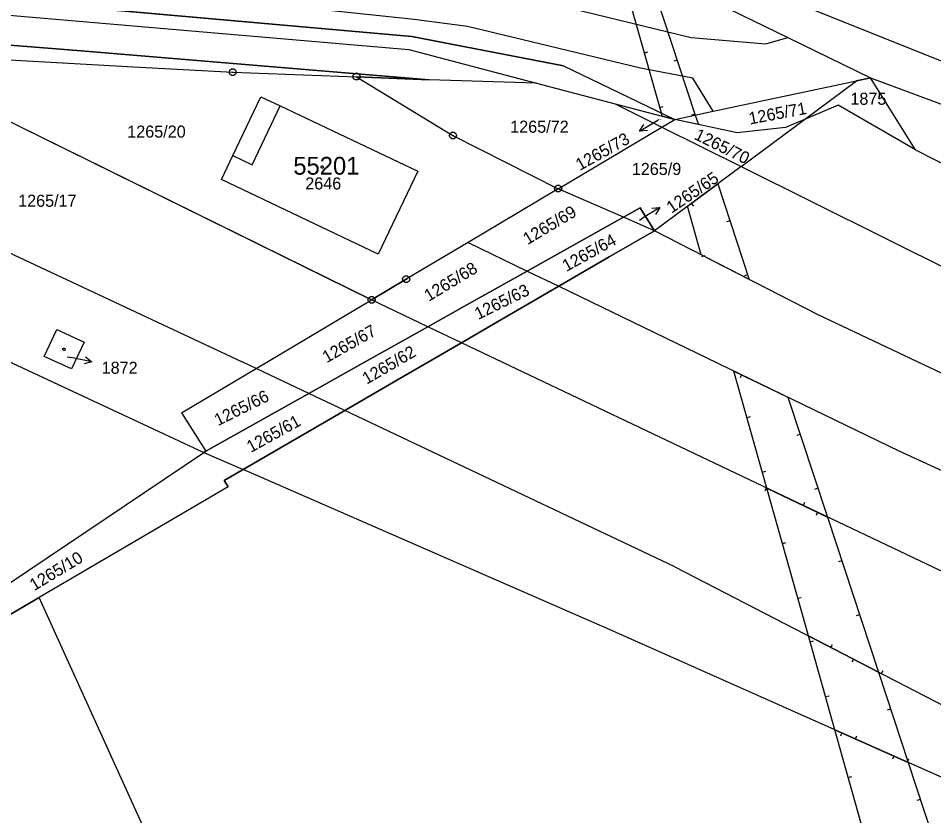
# Model space of a CAD drawing. Extents: x -779618 to -776429, y -1144546 to -1143350.
# Drawn here: x -777090.7 to -776962, y -1143980.2 to -1143868 of the extents above; entities that cross this region are included whole.
import ezdxf

# ---------------------------------------------------------------- set-up
doc = ezdxf.new("R2010")
doc.units = 0
for name, color, linetype in [('1', 7, 'Continuous'), ('11', 7, 'Continuous'), ('12', 7, 'Continuous'), ('13', 7, 'Continuous'), ('2', 7, 'Continuous'), ('4', 7, 'Continuous'), ('5', 7, 'Continuous'), ('6', 7, 'Continuous'), ('7', 7, 'Continuous'), ('8', 7, 'Continuous')]:
    doc.layers.add(name, color=color, linetype=linetype)

msp = doc.modelspace()

# ---------------------------------------------------------------- linework, layer by layer
at = {"layer": '1'}
for p, q in [((-777035.36, -1143870.54), (-777167.58, -1143858.82)), ((-777002.25, -1143861.05), (-776982.48, -1143870.69)), ((-777150.77, -1143862.48), (-777035.76, -1143872.38)), ((-777082.45, -1143872.54), (-777124.98, -1143869.13)), ((-777014.02, -1143874.66), (-777035.36, -1143870.54)), ((-776982.48, -1143870.69), (-776970.83, -1143876.37)), ((-777032.92, -1143876.65), (-777082.45, -1143872.54)), ((-777035.76, -1143872.38), (-777017.82, -1143877.1)), ((-777098.28, -1143873.49), (-777074.51, -1143874.84)), ((-777074.51, -1143874.84), (-777060.56, -1143875.59)), ((-777014.02, -1143874.66), (-776998.39, -1143882.22)), ((-777060.56, -1143875.59), (-777043.14, -1143876.21)), ((-777043.14, -1143876.21), (-777032.92, -1143876.65)), ((-777043.14, -1143876.21), (-777029.58, -1143884.49)), ((-777017.82, -1143877.1), (-777032.92, -1143876.65)), ((-776970.83, -1143876.37), (-776972.79, -1143876.78)), ((-776964.5, -1143886.48), (-776970.83, -1143876.37)), ((-776970.83, -1143876.37), (-776959.34, -1143880.62)), ((-777017.82, -1143877.1), (-777006.74, -1143880.02)), ((-776992.99, -1143881.07), (-776972.79, -1143876.78)), ((-776980.14, -1143882.23), (-776972.79, -1143876.78)), ((-777100.29, -1143878.41), (-777041.02, -1143907.6)), ((-777060.52, -1143887.31), (-777056.58, -1143879.03)), ((-777056.58, -1143879.03), (-777053.88, -1143880.29)), ((-777053.88, -1143880.29), (-777034.53, -1143889.5)), ((-777006.74, -1143880.02), (-777000.18, -1143883.29)), ((-777006.74, -1143880.02), (-776998.39, -1143882.22)), ((-776975.37, -1143880.22), (-776980.14, -1143882.23)), ((-776964.5, -1143886.48), (-776975.37, -1143880.22)), ((-776998.39, -1143882.22), (-776992.99, -1143881.07)), ((-777000.18, -1143883.29), (-776998.39, -1143882.22)), ((-776989.59, -1143884.09), (-776998.39, -1143882.22)), ((-776989.05, -1143888.84), (-776980.14, -1143882.23)), ((-776980.14, -1143882.23), (-776982.79, -1143883.35)), ((-777014.77, -1143891.96), (-777000.18, -1143883.29)), ((-777000.18, -1143883.29), (-776989.05, -1143888.84)), ((-776982.79, -1143883.35), (-776989.59, -1143884.09)), ((-777126.53, -1143884.78), (-777059.22, -1143916.33)), ((-777029.58, -1143884.49), (-777014.77, -1143891.96)), ((-776964.5, -1143886.48), (-776923.23, -1143907.82)), ((-777062.13, -1143890.66), (-777060.52, -1143887.31)), ((-777034.53, -1143889.5), (-777040.08, -1143901.18)), ((-776989.05, -1143888.84), (-777001.23, -1143897.87)), ((-776989.05, -1143888.84), (-776905.56, -1143930.42)), ((-777040.08, -1143901.18), (-777062.13, -1143890.66)), ((-777014.77, -1143891.96), (-777020.38, -1143895.3)), ((-777005.59, -1143895.97), (-777014.77, -1143891.96)), ((-777003.26, -1143894.66), (-777005.59, -1143895.97)), ((-777001.23, -1143897.87), (-777003.26, -1143894.66)), ((-777020.38, -1143895.3), (-777027.46, -1143899.52)), ((-777005.59, -1143895.97), (-777011.86, -1143899.48)), ((-777001.23, -1143897.87), (-777005.59, -1143895.97)), ((-777007.6, -1143901.57), (-777001.23, -1143897.87)), ((-776978.29, -1143909.65), (-777001.23, -1143897.87)), ((-777027.46, -1143899.52), (-777036.15, -1143904.69)), ((-777027.46, -1143899.52), (-777019.12, -1143903.55)), ((-777011.86, -1143899.48), (-777019.12, -1143903.55)), ((-777014.7, -1143905.69), (-777007.6, -1143901.57)), ((-777019.12, -1143903.55), (-777028.04, -1143908.55)), ((-777019.12, -1143903.55), (-777014.7, -1143905.69)), ((-777041.02, -1143907.6), (-777036.15, -1143904.69)), ((-777023.42, -1143910.75), (-777014.7, -1143905.69)), ((-777014.7, -1143905.69), (-776966.84, -1143928.84)), ((-777050.08, -1143912.98), (-777041.02, -1143907.6)), ((-777033.09, -1143911.38), (-777041.02, -1143907.6)), ((-777108.64, -1143908.55), (-777064.63, -1143929.09)), ((-777028.04, -1143908.55), (-777033.09, -1143911.38)), ((-776942.03, -1143926.84), (-776978.29, -1143909.65)), ((-777033.09, -1143911.38), (-777042.34, -1143916.56)), ((-777028.37, -1143913.63), (-777033.09, -1143911.38)), ((-777028.37, -1143913.63), (-777023.42, -1143910.75)), ((-777087.1, -1143915.56), (-777085.29, -1143911.77)), ((-777085.29, -1143911.77), (-777081.43, -1143913.56)), ((-777081.43, -1143913.56), (-777083.22, -1143917.29)), ((-777057.27, -1143917.26), (-777050.08, -1143912.98)), ((-777037.37, -1143918.86), (-777028.37, -1143913.63)), ((-776917.2, -1143966.59), (-777028.37, -1143913.63)), ((-777083.22, -1143917.29), (-777087.1, -1143915.56)), ((-777057.27, -1143917.26), (-777059.22, -1143916.33)), ((-777042.34, -1143916.56), (-777049.85, -1143920.77)), ((-777067.77, -1143923.5), (-777057.27, -1143917.26)), ((-777049.85, -1143920.77), (-777057.27, -1143917.26)), ((-777044.79, -1143923.17), (-777037.37, -1143918.86)), ((-777049.85, -1143920.77), (-777064.35, -1143928.9)), ((-777044.79, -1143923.17), (-777049.85, -1143920.77)), ((-777067.77, -1143923.5), (-777064.35, -1143928.9)), ((-777059.08, -1143931.47), (-777044.79, -1143923.17)), ((-776998.38, -1143945.16), (-777044.79, -1143923.17)), ((-777092.08, -1143947.56), (-777064.63, -1143929.09)), ((-777064.35, -1143928.9), (-777064.63, -1143929.09)), ((-777064.63, -1143929.09), (-777059.08, -1143931.47)), ((-776966.84, -1143928.84), (-776887.84, -1143965.39)), ((-777061.75, -1143933.02), (-777059.08, -1143931.47)), ((-777007.46, -1143954.02), (-777059.08, -1143931.47)), ((-777061.19, -1143933.89), (-777061.75, -1143933.02)), ((-777061.19, -1143933.89), (-777087.76, -1143949.47)), ((-776998.38, -1143945.16), (-776884.37, -1144004.05)), ((-777093.52, -1143952.82), (-777087.76, -1143949.47)), ((-777045.94, -1144041.58), (-777087.76, -1143949.47)), ((-776949.67, -1143979.74), (-777007.46, -1143954.02))]:
    msp.add_line(p, q, dxfattribs=at)
at = {"layer": '11'}
for points in [[(-777521.49, -1143753.86), (-777515.73, -1143755.37), (-777494.83, -1143763.84), (-777474.95, -1143771.88), (-777437.2, -1143787.51), (-777405.54, -1143800.83), (-777387.68, -1143807.89), (-777356.13, -1143823.03), (-777352.24, -1143824.36), (-777344.73, -1143827.04), (-777336.84, -1143829.8), (-777324.83, -1143836.1), (-777303.85, -1143844.86), (-777292.27, -1143847.75), (-777289.53, -1143848.43), (-777281.88, -1143848.9), (-777167.58, -1143858.82), (-777035.36, -1143870.54), (-777014.02, -1143874.66), (-776998.39, -1143882.22), (-776992.99, -1143881.07), (-776972.79, -1143876.78), (-776970.83, -1143876.37), (-776959.34, -1143880.62)], [(-777124.98, -1143869.13), (-777082.45, -1143872.54), (-777032.92, -1143876.65), (-777043.14, -1143876.21), (-777029.58, -1143884.49), (-777014.77, -1143891.96), (-777020.38, -1143895.3), (-777027.46, -1143899.52), (-777036.15, -1143904.69), (-777041.02, -1143907.6), (-777100.29, -1143878.41)], [(-777108.64, -1143908.55), (-777064.63, -1143929.09), (-777064.35, -1143928.9), (-777049.85, -1143920.77), (-777042.34, -1143916.56), (-777033.09, -1143911.38), (-777028.04, -1143908.55), (-777019.12, -1143903.55), (-777011.86, -1143899.48), (-777005.59, -1143895.97), (-777003.26, -1143894.66), (-777001.23, -1143897.87), (-777007.6, -1143901.57), (-777014.7, -1143905.69), (-777023.42, -1143910.75), (-777028.37, -1143913.63), (-777037.37, -1143918.86), (-777044.79, -1143923.17), (-777059.08, -1143931.47), (-777061.75, -1143933.02), (-777061.19, -1143933.89), (-777087.76, -1143949.47), (-777093.52, -1143952.82)]]:
    msp.add_lwpolyline(points, dxfattribs=at)
msp.add_lwpolyline([(-777060.52, -1143887.31), (-777056.58, -1143879.03), (-777053.88, -1143880.29), (-777034.53, -1143889.5), (-777040.08, -1143901.18), (-777062.13, -1143890.66)], close=True, dxfattribs=at)
at = {"layer": '12'}
for p, q in [((-777057.81, -1143888.59), (-777053.88, -1143880.29)), ((-777053.88, -1143880.29), (-777034.53, -1143889.5)), ((-777062.13, -1143890.66), (-777060.52, -1143887.31)), ((-777060.52, -1143887.31), (-777057.81, -1143888.59)), ((-777034.53, -1143889.5), (-777040.08, -1143901.18)), ((-777040.08, -1143901.18), (-777062.13, -1143890.66)), ((-777087.1, -1143915.56), (-777085.29, -1143911.77)), ((-777085.29, -1143911.77), (-777081.43, -1143913.56)), ((-777081.43, -1143913.56), (-777083.22, -1143917.29)), ((-777083.22, -1143917.29), (-777087.1, -1143915.56))]:
    msp.add_line(p, q, dxfattribs=at)
at = {"layer": '13'}
for p, q in [((-777002.64, -1143872.84), (-777002.16, -1143872.71)), ((-776998.03, -1143873.87), (-776998.51, -1143874.03)), ((-777000.48, -1143880.54), (-777000, -1143880.41)), ((-776995.53, -1143881.47), (-776996.01, -1143881.63)), ((-776996.06, -1143894.04), (-776995.76, -1143894.44)), ((-776990.6, -1143896.48), (-776991.08, -1143896.64)), ((-776994.58, -1143901.51), (-776994.1, -1143901.37)), ((-776988.1, -1143904.08), (-776988.57, -1143904.24)), ((-776988.97, -1143918.13), (-776989.19, -1143918.58)), ((-776988.21, -1143924.16), (-776987.73, -1143924.02)), ((-776980.73, -1143926.51), (-776981.21, -1143926.67)), ((-776986.04, -1143931.86), (-776985.56, -1143931.72)), ((-776985.5, -1143934.05), (-776985.71, -1143934.5)), ((-776978.23, -1143934.11), (-776978.7, -1143934.27)), ((-776980.28, -1143936.54), (-776980.07, -1143936.08)), ((-776978.28, -1143937.49), (-776978.49, -1143937.95)), ((-776983.22, -1143941.88), (-776982.74, -1143941.75)), ((-776974.88, -1143944.3), (-776975.35, -1143944.46)), ((-776981.06, -1143949.58), (-776980.58, -1143949.45)), ((-776972.38, -1143951.9), (-776972.85, -1143952.06)), ((-776979.33, -1143955.72), (-776978.85, -1143955.59)), ((-776976.41, -1143956.51), (-776976.18, -1143956.07)), ((-776973.24, -1143958.15), (-776973.47, -1143958.59)), ((-776969.3, -1143960.18), (-776969.07, -1143959.74)), ((-776977.16, -1143963.42), (-776976.68, -1143963.29)), ((-776968.01, -1143965.18), (-776968.49, -1143965.34)), ((-776974.88, -1143968.52), (-776975.08, -1143968.98)), ((-776972.97, -1143969.37), (-776972.77, -1143968.91)), ((-776967.57, -1143971.77), (-776967.77, -1143972.23)), ((-776965.66, -1143972.62), (-776965.46, -1143972.16)), ((-776973.97, -1143974.77), (-776973.49, -1143974.63)), ((-776963.83, -1143977.89), (-776964.31, -1143978.05))]:
    msp.add_line(p, q, dxfattribs=at)
for points in [[(-777002.25, -1143861.05), (-776995.49, -1143881.6), (-776995.06, -1143882.93), (-776998.39, -1143882.22), (-777000.13, -1143881.76), (-777000.26, -1143881.32), (-777006.04, -1143860.76)], [(-776992.32, -1143891.26), (-776987.89, -1143904.72), (-776994.65, -1143901.25), (-776996.57, -1143894.42)], [(-776982.45, -1143921.29), (-776976.9, -1143938.15), (-776985.41, -1143934.09), (-776990.05, -1143917.61)], [(-776979.57, -1143954.88), (-776985.41, -1143934.09), (-776976.9, -1143938.15), (-776969.73, -1143959.96)], [(-776969.73, -1143959.96), (-776965.55, -1143972.67), (-776975.85, -1143968.09), (-776979.57, -1143954.88)], [(-776965.55, -1143972.67), (-776924.49, -1144097.58), (-776941.86, -1144088.96), (-776975.85, -1143968.09)]]:
    msp.add_lwpolyline(points, close=True, dxfattribs=at)
at = {"layer": '4'}
for p, q in [((-777035.05, -1143868.16), (-777051.48, -1143866.41)), ((-777018.06, -1143865.29), (-776996.07, -1143870.7)), ((-777027.55, -1143869.14), (-777035.05, -1143868.16)), ((-777003.19, -1143875), (-777027.55, -1143869.14)), ((-776996.07, -1143870.7), (-776985.59, -1143871.58)), ((-776985.59, -1143871.58), (-776982.48, -1143870.69)), ((-776995.85, -1143876.42), (-777003.19, -1143875)), ((-776992.99, -1143881.07), (-776995.85, -1143876.42)), ((-777057.81, -1143888.59), (-777053.88, -1143880.29)), ((-777060.52, -1143887.31), (-777057.81, -1143888.59))]:
    msp.add_line(p, q, dxfattribs=at)
at = {"layer": '5'}
for points in [[(-777047.98, -1143888.75), (-777047.88, -1143888.77), (-777047.83, -1143888.86), (-777047.81, -1143888.92), (-777047.83, -1143889.01), (-777047.91, -1143889.08), (-777047.98, -1143889.09), (-777048.07, -1143889.06), (-777048.13, -1143889), (-777048.15, -1143888.92), (-777048.13, -1143888.83), (-777048.05, -1143888.76)], [(-777084.29, -1143914.38), (-777084.19, -1143914.4), (-777084.14, -1143914.49), (-777084.12, -1143914.55), (-777084.14, -1143914.64), (-777084.22, -1143914.71), (-777084.29, -1143914.72), (-777084.38, -1143914.69), (-777084.44, -1143914.63), (-777084.46, -1143914.55), (-777084.44, -1143914.46), (-777084.36, -1143914.39)]]:
    msp.add_lwpolyline(points, close=True, dxfattribs=at)
at = {"layer": '6'}
msp.add_line((-776862.57, -1143913.55), (-777015.55, -1143852.07), dxfattribs=at)
at = {"layer": '7'}
for p, q in [((-777003.35, -1143883.88), (-777000.78, -1143882.32)), ((-777000.66, -1143882.24), (-777000.78, -1143882.32)), ((-777000.49, -1143894.63), (-777003.05, -1143896.19)), ((-777003.35, -1143896.37), (-777003.05, -1143896.19)), ((-777083.82, -1143915.63), (-777083.32, -1143915.73)), ((-777080.38, -1143916.3), (-777083.32, -1143915.73))]:
    msp.add_line(p, q, dxfattribs=at)
for points in [[(-777002.23, -1143883.78), (-777003.35, -1143883.88), (-777002.75, -1143882.93)], [(-777001.6, -1143894.72), (-777000.49, -1143894.63), (-777001.08, -1143895.58)], [(-777081.26, -1143915.62), (-777080.38, -1143916.3), (-777081.45, -1143916.6)]]:
    msp.add_lwpolyline(points, dxfattribs=at)
at = {"layer": '8'}
for p, q in [((-777060.68, -1143875.59), (-777060.44, -1143875.59)), ((-777043.26, -1143876.21), (-777043.02, -1143876.21)), ((-777029.7, -1143884.49), (-777029.46, -1143884.49)), ((-777014.89, -1143891.96), (-777014.65, -1143891.96)), ((-777036.27, -1143904.69), (-777036.03, -1143904.69)), ((-777041.14, -1143907.6), (-777040.9, -1143907.6))]:
    msp.add_line(p, q, dxfattribs=at)
for points in [[(-777060.41, -1143875.11), (-777060.16, -1143875.29), (-777060.06, -1143875.58), (-777060.16, -1143875.87), (-777060.41, -1143876.05), (-777060.72, -1143876.05), (-777060.97, -1143875.87), (-777061.07, -1143875.58), (-777060.97, -1143875.29), (-777060.72, -1143875.11)], [(-777042.99, -1143875.73), (-777042.74, -1143875.91), (-777042.64, -1143876.2), (-777042.74, -1143876.49), (-777042.99, -1143876.67), (-777043.3, -1143876.67), (-777043.55, -1143876.49), (-777043.65, -1143876.2), (-777043.55, -1143875.91), (-777043.3, -1143875.73)], [(-777029.43, -1143884.01), (-777029.18, -1143884.19), (-777029.08, -1143884.48), (-777029.18, -1143884.77), (-777029.43, -1143884.95), (-777029.74, -1143884.95), (-777029.99, -1143884.77), (-777030.09, -1143884.48), (-777029.99, -1143884.19), (-777029.74, -1143884.01)], [(-777014.62, -1143891.48), (-777014.37, -1143891.66), (-777014.27, -1143891.95), (-777014.37, -1143892.24), (-777014.62, -1143892.42), (-777014.93, -1143892.42), (-777015.18, -1143892.24), (-777015.28, -1143891.95), (-777015.18, -1143891.66), (-777014.93, -1143891.48)], [(-777036, -1143904.21), (-777035.75, -1143904.39), (-777035.65, -1143904.68), (-777035.75, -1143904.97), (-777036, -1143905.15), (-777036.31, -1143905.15), (-777036.56, -1143904.97), (-777036.66, -1143904.68), (-777036.56, -1143904.39), (-777036.31, -1143904.21)], [(-777040.87, -1143907.12), (-777040.62, -1143907.3), (-777040.52, -1143907.59), (-777040.62, -1143907.88), (-777040.87, -1143908.06), (-777041.18, -1143908.06), (-777041.43, -1143907.88), (-777041.53, -1143907.59), (-777041.43, -1143907.3), (-777041.18, -1143907.12)]]:
    msp.add_lwpolyline(points, close=True, dxfattribs=at)

# ---------------------------------------------------------------- texts
at = {"layer": '11'}
msp.add_text('55201', height=2.5, dxfattribs=at).set_placement((-777052.03, -1143889.99))
at = {"layer": '2'}
for s, height, p in [('1875', 1.7, (-776973.67, -1143880.16)), ('1265/20', 1.7, (-777075.39, -1143884.78)), ('1265/72', 1.7, (-777021.52, -1143884.09)), ('1265/73', 0.1, (-777000.64, -1143882.24)), ('1265/9', 1.7, (-777004.42, -1143890.04)), ('2646', 1.7, (-777050.35, -1143892.07)), ('1265/17', 1.7, (-777090.74, -1143894.51)), ('1265/65', 0.1, (-777003.33, -1143896.37)), ('1872', 0.1, (-777083.8, -1143915.63))]:
    msp.add_text(s, height=height, dxfattribs=at).set_placement(p)
for s, rotation, p in [('1265/71', 10.5424, (-776987.8, -1143882.94)), ('1265/70', 333.6906, (-776995.77, -1143884.93)), ('1265/69', 30.8824, (-777019.08, -1143899.91)), ('1265/64', 28.9917, (-777013.61, -1143903.68)), ('1265/68', 31.2262, (-777032.98, -1143907.89)), ('1265/63', 26.1269, (-777026.02, -1143910.43)), ('1265/67', 29.5646, (-777047.34, -1143916.53)), ('1265/62', 30.2522, (-777041.71, -1143919.55)), ('1265/66', 26.4134, (-777062.63, -1143925.38)), ('1265/61', 28.9344, (-777058.01, -1143929.15)), ('1265/10', 31.1116, (-777088.48, -1143948.59))]:
    msp.add_text(s, height=1.7, rotation=rotation, dxfattribs=at).set_placement(p)
at = {"layer": '7'}
for s, rotation, p in [('1265/73', 29.1636, (-777011.72, -1143889.47)), ('1265/65', 34.2056, (-776998.82, -1143895.49))]:
    msp.add_text(s, height=1.7, rotation=rotation, dxfattribs=at).set_placement(p)
msp.add_text('1872', height=1.7, dxfattribs=at).set_placement((-777078.99, -1143918))

doc.saveas('drawing.dxf')
